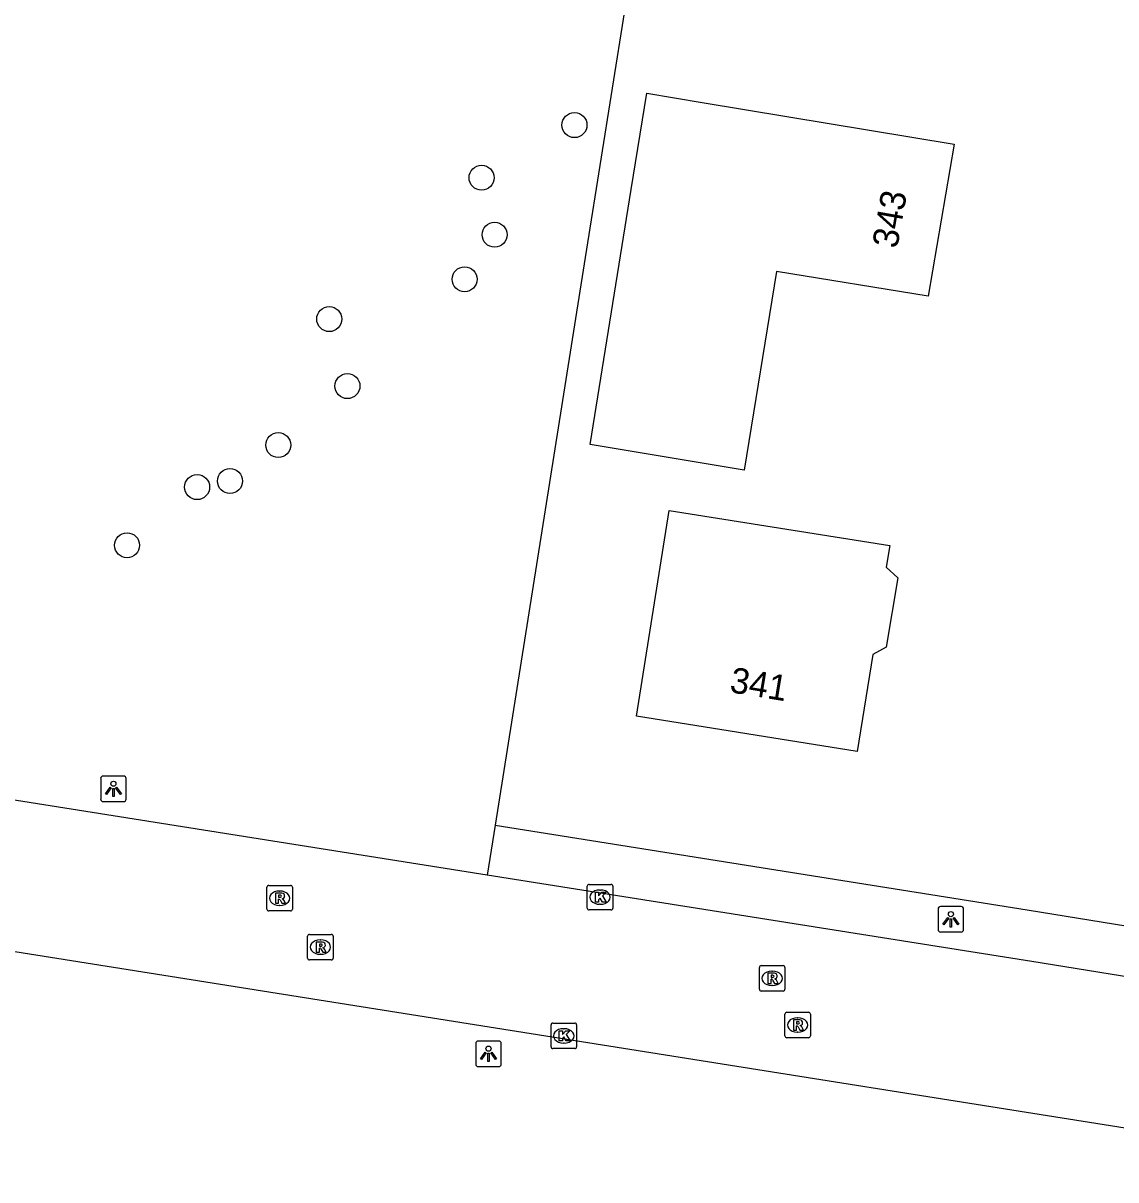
# Model space of a CAD drawing. Extents: x 154324 to 155743, y 382939 to 384183.
# Drawn here: x 155304.56 to 155347.33, y 383376.46 to 383421.74 of the extents above; entities that cross this region are included whole.
import ezdxf

# ---------------------------------------------------------------- set-up
doc = ezdxf.new("R2010")
doc.units = 0
for name, color, linetype in [('IMGEO_Boom', 7, 'Continuous'), ('IMGEO_Groenvoorziening', 7, 'Continuous'), ('IMGEO_Kolk', 7, 'Continuous'), ('IMGEO_Lichtpunt', 7, 'Continuous'), ('IMGEO_Pand', 7, 'Continuous'), ('IMGEO_Pand_nummerreeks', 7, 'Continuous'), ('IMGEO_Rijbaan_lokaal_gesloten', 7, 'Continuous'), ('IMGEO_Rioolput', 7, 'Continuous'), ('IMGEO_Voetpad_open', 7, 'Continuous')]:
    doc.layers.add(name, color=color, linetype=linetype)

msp = doc.modelspace()

# ---------------------------------------------------------------- linework, layer by layer
at = {"layer": 'IMGEO_Boom'}
for centre in [(155326.14, 383417.747), (155322.503, 383415.689), (155323.014, 383413.457), (155321.841, 383411.714), (155316.542, 383410.153), (155317.255, 383407.532), (155314.547, 383405.225), (155311.374, 383403.579), (155312.659, 383403.817), (155308.63, 383401.303)]:
    msp.add_circle(centre, 0.489, dxfattribs=at)
at = {"layer": 'IMGEO_Groenvoorziening'}
msp.add_lwpolyline([(155333.894, 383463.145), (155328.096, 383422.22), (155326.654, 383413.134), (155323.037, 383390.342)], dxfattribs=at)
at = {"layer": 'IMGEO_Kolk'}
for p, q in [((155326.639, 383387.103), (155326.639, 383387.955)), ((155326.714, 383388.029), (155327.566, 383388.029)), ((155327.127, 383387.809), (155327.152, 383387.809)), ((155327.64, 383387.955), (155327.64, 383387.103)), ((155327.15, 383387.249), (155327.125, 383387.249)), ((155327.566, 383387.029), (155326.714, 383387.029)), ((155325.221, 383381.674), (155325.221, 383382.526)), ((155325.296, 383382.6), (155326.148, 383382.6)), ((155325.709, 383382.38), (155325.734, 383382.38)), ((155326.222, 383382.526), (155326.222, 383381.674)), ((155325.732, 383381.82), (155325.707, 383381.82)), ((155326.148, 383381.6), (155325.296, 383381.6))]:
    msp.add_line(p, q, dxfattribs=at)
for points in [[(155326.639, 383387.103), (155326.639, 383387.955)], [(155326.714, 383388.029), (155327.566, 383388.029)], [(155326.96, 383387.729), (155327.083, 383387.729), (155327.083, 383387.578), (155327.213, 383387.729), (155327.377, 383387.729), (155327.231, 383387.578), (155327.384, 383387.329), (155327.232, 383387.329), (155327.147, 383387.493), (155327.083, 383387.426), (155327.083, 383387.329), (155326.96, 383387.329), (155326.96, 383387.729)], [(155327.64, 383387.955), (155327.64, 383387.103)], [(155327.566, 383387.029), (155326.714, 383387.029)], [(155325.221, 383381.674), (155325.221, 383382.526)], [(155325.296, 383382.6), (155326.148, 383382.6)], [(155325.542, 383382.3), (155325.665, 383382.3), (155325.665, 383382.149), (155325.795, 383382.3), (155325.959, 383382.3), (155325.813, 383382.149), (155325.966, 383381.9), (155325.814, 383381.9), (155325.729, 383382.064), (155325.665, 383381.997), (155325.665, 383381.9), (155325.542, 383381.9), (155325.542, 383382.3)], [(155326.222, 383382.526), (155326.222, 383381.674)], [(155326.148, 383381.6), (155325.296, 383381.6)]]:
    msp.add_lwpolyline(points, dxfattribs=at)
for centre, start, end in [((155326.716, 383387.953), 91.552, 178.448), ((155326.716, 383387.953), 91.552, 178.448), ((155327.564, 383387.953), 1.552, 88.448), ((155327.564, 383387.953), 1.552, 88.448), ((155326.716, 383387.105), 181.552, 268.448), ((155326.716, 383387.105), 181.552, 268.448), ((155327.564, 383387.105), 271.552, 358.448), ((155327.564, 383387.105), 271.552, 358.448), ((155325.298, 383382.524), 91.552, 178.448), ((155325.298, 383382.524), 91.552, 178.448), ((155326.146, 383382.524), 1.552, 88.448), ((155326.146, 383382.524), 1.552, 88.448), ((155325.298, 383381.676), 181.552, 268.448), ((155325.298, 383381.676), 181.552, 268.448), ((155326.146, 383381.676), 271.552, 358.448), ((155326.146, 383381.676), 271.552, 358.448)]:
    msp.add_arc(centre, 0.0765, start, end, dxfattribs=at)
for centre, major_axis, ratio, start_param, end_param in [((155327.126, 383387.529), (-0.387, 0.002), 0.722429, 4.712389, 7.853982), ((155327.151, 383387.529), (-0.39, 0.002), 0.717154, 1.570796, 4.712389), ((155325.708, 383382.1), (-0.387, 0.002), 0.722429, 4.712389, 7.853982), ((155325.733, 383382.1), (-0.39, 0.002), 0.717154, 1.570796, 4.712389)]:
    msp.add_ellipse(centre, major_axis=major_axis, ratio=ratio, start_param=start_param, end_param=end_param, dxfattribs=at)
at = {"layer": 'IMGEO_Lichtpunt'}
for p, q in [((155307.598, 383392.172), (155307.598, 383391.365)), ((155307.598, 383392.172), (155307.598, 383391.365)), ((155308.5, 383392.267), (155307.692, 383392.267)), ((155308.5, 383392.267), (155307.692, 383392.267)), ((155308.594, 383391.365), (155308.594, 383392.172)), ((155308.594, 383391.365), (155308.594, 383392.172)), ((155307.692, 383391.271), (155308.5, 383391.271)), ((155307.692, 383391.271), (155308.5, 383391.271)), ((155340.371, 383387.067), (155340.371, 383386.26)), ((155340.371, 383387.067), (155340.371, 383386.26)), ((155341.273, 383387.162), (155340.465, 383387.162)), ((155341.273, 383387.162), (155340.465, 383387.162)), ((155341.367, 383386.26), (155341.367, 383387.067)), ((155341.367, 383386.26), (155341.367, 383387.067)), ((155340.465, 383386.166), (155341.273, 383386.166)), ((155340.465, 383386.166), (155341.273, 383386.166)), ((155322.276, 383381.801), (155322.276, 383380.994)), ((155322.276, 383381.801), (155322.276, 383380.994)), ((155323.178, 383381.896), (155322.37, 383381.896)), ((155323.178, 383381.896), (155322.37, 383381.896)), ((155323.272, 383380.994), (155323.272, 383381.801)), ((155323.272, 383380.994), (155323.272, 383381.801)), ((155322.37, 383380.9), (155323.178, 383380.9)), ((155322.37, 383380.9), (155323.178, 383380.9))]:
    msp.add_line(p, q, dxfattribs=at)
for points in [[(155307.972, 383391.836), (155308.011, 383391.808), (155307.823, 383391.546), (155307.785, 383391.573), (155307.972, 383391.836)], [(155308.074, 383391.788), (155308.121, 383391.788), (155308.121, 383391.466), (155308.074, 383391.466), (155308.074, 383391.788)], [(155308.184, 383391.808), (155308.222, 383391.835), (155308.409, 383391.573), (155308.37, 383391.545), (155308.184, 383391.808)], [(155340.745, 383386.731), (155340.784, 383386.703), (155340.596, 383386.441), (155340.558, 383386.468), (155340.745, 383386.731)], [(155340.957, 383386.703), (155340.995, 383386.73), (155341.182, 383386.468), (155341.143, 383386.44), (155340.957, 383386.703)], [(155340.847, 383386.683), (155340.894, 383386.683), (155340.894, 383386.361), (155340.847, 383386.361), (155340.847, 383386.683)], [(155322.65, 383381.465), (155322.689, 383381.437), (155322.501, 383381.175), (155322.463, 383381.202), (155322.65, 383381.465)], [(155322.752, 383381.417), (155322.799, 383381.417), (155322.799, 383381.095), (155322.752, 383381.095), (155322.752, 383381.417)], [(155322.862, 383381.437), (155322.9, 383381.464), (155323.087, 383381.202), (155323.048, 383381.174), (155322.862, 383381.437)]]:
    msp.add_lwpolyline(points, dxfattribs=at)
for centre in [(155308.097, 383391.97), (155340.87, 383386.865), (155322.775, 383381.599)]:
    msp.add_circle(centre, 0.0994, dxfattribs=at)
for centre, start, end in [((155307.692, 383392.172), 90, 180), ((155307.692, 383392.172), 90, 180), ((155308.5, 383392.172), 0, 90), ((155308.5, 383392.172), 0, 90), ((155307.692, 383391.365), 180, 270), ((155307.692, 383391.365), 180, 270), ((155308.5, 383391.365), 270, 0), ((155308.5, 383391.365), 270, 360), ((155340.465, 383387.067), 90, 180), ((155340.465, 383387.067), 90, 180), ((155341.273, 383387.067), 0, 90), ((155341.273, 383387.067), 0, 90), ((155340.465, 383386.26), 180, 270), ((155340.465, 383386.26), 180, 270), ((155341.273, 383386.26), 270, 0), ((155341.273, 383386.26), 270, 360), ((155322.37, 383381.801), 90, 180), ((155322.37, 383381.801), 90, 180), ((155323.178, 383381.801), 0, 90), ((155323.178, 383381.801), 0, 90), ((155322.37, 383380.994), 180, 270), ((155322.37, 383380.994), 180, 270), ((155323.178, 383380.994), 270, 0), ((155323.178, 383380.994), 270, 360)]:
    msp.add_arc(centre, 0.0946, start, end, dxfattribs=at)
at = {"layer": 'IMGEO_Pand'}
for points in [[(155331.132, 383418.635), (155341.002, 383417.002), (155339.981, 383411.056), (155334.042, 383412.019), (155332.779, 383404.244), (155326.749, 383405.241), (155328.358, 383415.227), (155328.965, 383418.993), (155331.132, 383418.635)], [(155338.798, 383400.032), (155338.334, 383397.31), (155337.818, 383397.031), (155337.196, 383393.228), (155328.566, 383394.611), (155329.846, 383402.667), (155338.478, 383401.295), (155338.343, 383400.445), (155338.798, 383400.032)]]:
    msp.add_lwpolyline(points, dxfattribs=at)
at = {"layer": 'IMGEO_Rijbaan_lokaal_gesloten'}
for points in [[(155322.727, 383388.39), (155286.115, 383394.2), (155241.462, 383401.286)], [(155348.398, 383384.302), (155344.042, 383385.007), (155322.727, 383388.39)], [(155360.426, 383376.464), (155295.925, 383386.713)]]:
    msp.add_lwpolyline(points, dxfattribs=at)
at = {"layer": 'IMGEO_Rioolput'}
for p, q in [((155314.102, 383387.062), (155314.102, 383387.914)), ((155314.177, 383387.988), (155315.029, 383387.988)), ((155314.59, 383387.768), (155314.615, 383387.768)), ((155315.103, 383387.914), (155315.103, 383387.062)), ((155314.613, 383387.208), (155314.588, 383387.208)), ((155315.029, 383386.988), (155314.177, 383386.988)), ((155315.696, 383385.147), (155315.696, 383385.999)), ((155315.771, 383386.073), (155316.623, 383386.073)), ((155316.184, 383385.853), (155316.209, 383385.853)), ((155316.697, 383385.999), (155316.697, 383385.147)), ((155316.623, 383385.073), (155315.771, 383385.073)), ((155316.207, 383385.293), (155316.182, 383385.293)), ((155333.375, 383383.926), (155333.375, 383384.778)), ((155333.45, 383384.852), (155334.302, 383384.852)), ((155333.863, 383384.632), (155333.888, 383384.632)), ((155334.376, 383384.778), (155334.376, 383383.926)), ((155333.886, 383384.072), (155333.861, 383384.072)), ((155334.302, 383383.852), (155333.45, 383383.852)), ((155334.371, 383382.101), (155334.371, 383382.953)), ((155334.446, 383383.027), (155335.298, 383383.027)), ((155334.859, 383382.807), (155334.884, 383382.807)), ((155335.372, 383382.953), (155335.372, 383382.101)), ((155334.882, 383382.247), (155334.857, 383382.247)), ((155335.298, 383382.027), (155334.446, 383382.027))]:
    msp.add_line(p, q, dxfattribs=at)
for points in [[(155314.102, 383387.062), (155314.102, 383387.914)], [(155314.177, 383387.988), (155315.029, 383387.988)], [(155314.691, 383387.686), (155314.439, 383387.688), (155314.439, 383387.288)], [(155315.103, 383387.914), (155315.103, 383387.062)], [(155314.439, 383387.288), (155314.563, 383387.288), (155314.563, 383387.45), (155314.574, 383387.45)], [(155314.617, 383387.607), (155314.563, 383387.607), (155314.563, 383387.526)], [(155314.563, 383387.526), (155314.615, 383387.526)], [(155314.621, 383387.421), (155314.692, 383387.288), (155314.832, 383387.288), (155314.767, 383387.414)], [(155315.029, 383386.988), (155314.177, 383386.988)], [(155315.696, 383385.147), (155315.696, 383385.999)], [(155315.771, 383386.073), (155316.623, 383386.073)], [(155316.697, 383385.999), (155316.697, 383385.147)], [(155316.285, 383385.771), (155316.033, 383385.773), (155316.033, 383385.373)], [(155316.033, 383385.373), (155316.157, 383385.373), (155316.157, 383385.535), (155316.168, 383385.535)], [(155316.211, 383385.692), (155316.157, 383385.692), (155316.157, 383385.611)], [(155316.157, 383385.611), (155316.209, 383385.611)], [(155316.215, 383385.506), (155316.286, 383385.373), (155316.426, 383385.373), (155316.361, 383385.499)], [(155316.623, 383385.073), (155315.771, 383385.073)], [(155333.375, 383383.926), (155333.375, 383384.778)], [(155333.45, 383384.852), (155334.302, 383384.852)], [(155333.964, 383384.55), (155333.712, 383384.552), (155333.712, 383384.152)], [(155333.89, 383384.471), (155333.836, 383384.471), (155333.836, 383384.39)], [(155334.376, 383384.778), (155334.376, 383383.926)], [(155333.712, 383384.152), (155333.836, 383384.152), (155333.836, 383384.314), (155333.847, 383384.314)], [(155333.836, 383384.39), (155333.888, 383384.39)], [(155333.894, 383384.285), (155333.965, 383384.152), (155334.105, 383384.152), (155334.04, 383384.278)], [(155334.302, 383383.852), (155333.45, 383383.852)], [(155334.371, 383382.101), (155334.371, 383382.953)], [(155334.446, 383383.027), (155335.298, 383383.027)], [(155334.96, 383382.725), (155334.708, 383382.727), (155334.708, 383382.327)], [(155335.372, 383382.953), (155335.372, 383382.101)], [(155334.708, 383382.327), (155334.832, 383382.327), (155334.832, 383382.489), (155334.843, 383382.489)], [(155334.886, 383382.646), (155334.832, 383382.646), (155334.832, 383382.565)], [(155334.832, 383382.565), (155334.884, 383382.565)], [(155334.89, 383382.46), (155334.961, 383382.327), (155335.101, 383382.327), (155335.036, 383382.453)], [(155335.298, 383382.027), (155334.446, 383382.027)]]:
    msp.add_lwpolyline(points, dxfattribs=at)
for centre, radius, start, end in [((155314.179, 383387.912), 0.0765, 91.552, 178.448), ((155314.179, 383387.912), 0.0765, 91.552, 178.448), ((155314.69, 383387.576), 0.109, 350.3612, 89.416), ((155315.027, 383387.912), 0.0765, 1.552, 88.448), ((155315.027, 383387.912), 0.0765, 1.552, 88.448), ((155314.573, 383387.397), 0.0533, 26.0293, 88.6989), ((155314.599, 383387.715), 0.19, 274.7715, 282.9687), ((155314.623, 383387.511), 0.0964, 77.0061, 93.1865), ((155314.637, 383387.568), 0.0378, 276.6634, 79.6772), ((155314.688, 383387.576), 0.112, 277.5842, 350.9817), ((155314.672, 383387.361), 0.108, 29.5134, 73.7905), ((155314.179, 383387.064), 0.0765, 181.552, 268.448), ((155314.179, 383387.064), 0.0765, 181.552, 268.448), ((155315.027, 383387.064), 0.0765, 271.552, 358.448), ((155315.027, 383387.064), 0.0765, 271.552, 358.448), ((155315.773, 383385.997), 0.0765, 91.552, 178.448), ((155315.773, 383385.997), 0.0765, 91.552, 178.448), ((155316.621, 383385.997), 0.0765, 1.552, 88.448), ((155316.621, 383385.997), 0.0765, 1.552, 88.448), ((155316.167, 383385.482), 0.0533, 26.0293, 88.6989), ((155316.193, 383385.8), 0.19, 274.7715, 282.9687), ((155316.217, 383385.596), 0.0964, 77.0061, 93.1865), ((155316.231, 383385.653), 0.0378, 276.6634, 79.6772), ((155316.284, 383385.661), 0.109, 350.3612, 89.416), ((155316.282, 383385.661), 0.112, 277.5842, 350.9817), ((155316.266, 383385.446), 0.108, 29.5134, 73.7905), ((155315.773, 383385.149), 0.0765, 181.552, 268.448), ((155315.773, 383385.149), 0.0765, 181.552, 268.448), ((155316.621, 383385.149), 0.0765, 271.552, 358.448), ((155316.621, 383385.149), 0.0765, 271.552, 358.448), ((155333.452, 383384.776), 0.0765, 91.552, 178.448), ((155333.452, 383384.776), 0.0765, 91.552, 178.448), ((155333.896, 383384.375), 0.0964, 77.0061, 93.1865), ((155333.91, 383384.432), 0.0378, 276.6634, 79.6772), ((155333.963, 383384.44), 0.109, 350.3612, 89.416), ((155334.3, 383384.776), 0.0765, 1.552, 88.448), ((155334.3, 383384.776), 0.0765, 1.552, 88.448), ((155333.846, 383384.261), 0.0533, 26.0293, 88.6989), ((155333.872, 383384.579), 0.19, 274.7715, 282.9687), ((155333.961, 383384.44), 0.112, 277.5842, 350.9817), ((155333.945, 383384.225), 0.108, 29.5134, 73.7905), ((155333.452, 383383.928), 0.0765, 181.552, 268.448), ((155333.452, 383383.928), 0.0765, 181.552, 268.448), ((155334.3, 383383.928), 0.0765, 271.552, 358.448), ((155334.3, 383383.928), 0.0765, 271.552, 358.448), ((155334.448, 383382.951), 0.0765, 91.552, 178.448), ((155334.448, 383382.951), 0.0765, 91.552, 178.448), ((155334.959, 383382.615), 0.109, 350.3612, 89.416), ((155335.296, 383382.951), 0.0765, 1.552, 88.448), ((155335.296, 383382.951), 0.0765, 1.552, 88.448), ((155334.842, 383382.436), 0.0533, 26.0293, 88.6989), ((155334.868, 383382.754), 0.19, 274.7715, 282.9687), ((155334.892, 383382.55), 0.0964, 77.0061, 93.1865), ((155334.906, 383382.607), 0.0378, 276.6634, 79.6772), ((155334.957, 383382.615), 0.112, 277.5842, 350.9817), ((155334.941, 383382.4), 0.108, 29.5134, 73.7905), ((155334.448, 383382.103), 0.0765, 181.552, 268.448), ((155334.448, 383382.103), 0.0765, 181.552, 268.448), ((155335.296, 383382.103), 0.0765, 271.552, 358.448), ((155335.296, 383382.103), 0.0765, 271.552, 358.448)]:
    msp.add_arc(centre, radius, start, end, dxfattribs=at)
for centre, major_axis, ratio, start_param, end_param in [((155314.589, 383387.488), (-0.387, 0.002), 0.722429, 4.712389, 7.853982), ((155314.614, 383387.488), (-0.39, 0.002), 0.717154, 1.570796, 4.712389), ((155316.183, 383385.573), (-0.387, 0.002), 0.722429, 4.712389, 7.853982), ((155316.208, 383385.573), (-0.39, 0.002), 0.717154, 1.570796, 4.712389), ((155333.862, 383384.352), (-0.387, 0.002), 0.722429, 4.712389, 7.853982), ((155333.887, 383384.352), (-0.39, 0.002), 0.717154, 1.570796, 4.712389), ((155334.858, 383382.527), (-0.387, 0.002), 0.722429, 4.712389, 7.853982), ((155334.883, 383382.527), (-0.39, 0.002), 0.717154, 1.570796, 4.712389)]:
    msp.add_ellipse(centre, major_axis=major_axis, ratio=ratio, start_param=start_param, end_param=end_param, dxfattribs=at)
at = {"layer": 'IMGEO_Voetpad_open'}
for points in [[(155323.037, 383390.342), (155322.727, 383388.39)], [(155323.037, 383390.342), (155343.85, 383387.039), (155363.801, 383383.796)]]:
    msp.add_lwpolyline(points, dxfattribs=at)

# ---------------------------------------------------------------- texts
at = {"layer": 'IMGEO_Pand_nummerreeks'}
for s, rotation, p in [('343', 80.0594, (155338.769, 383412.89)), ('341', 350.6952, (155332.178, 383395.556))]:
    msp.add_text(s, height=1, rotation=rotation, dxfattribs=at).set_placement(p)

doc.saveas('drawing.dxf')
